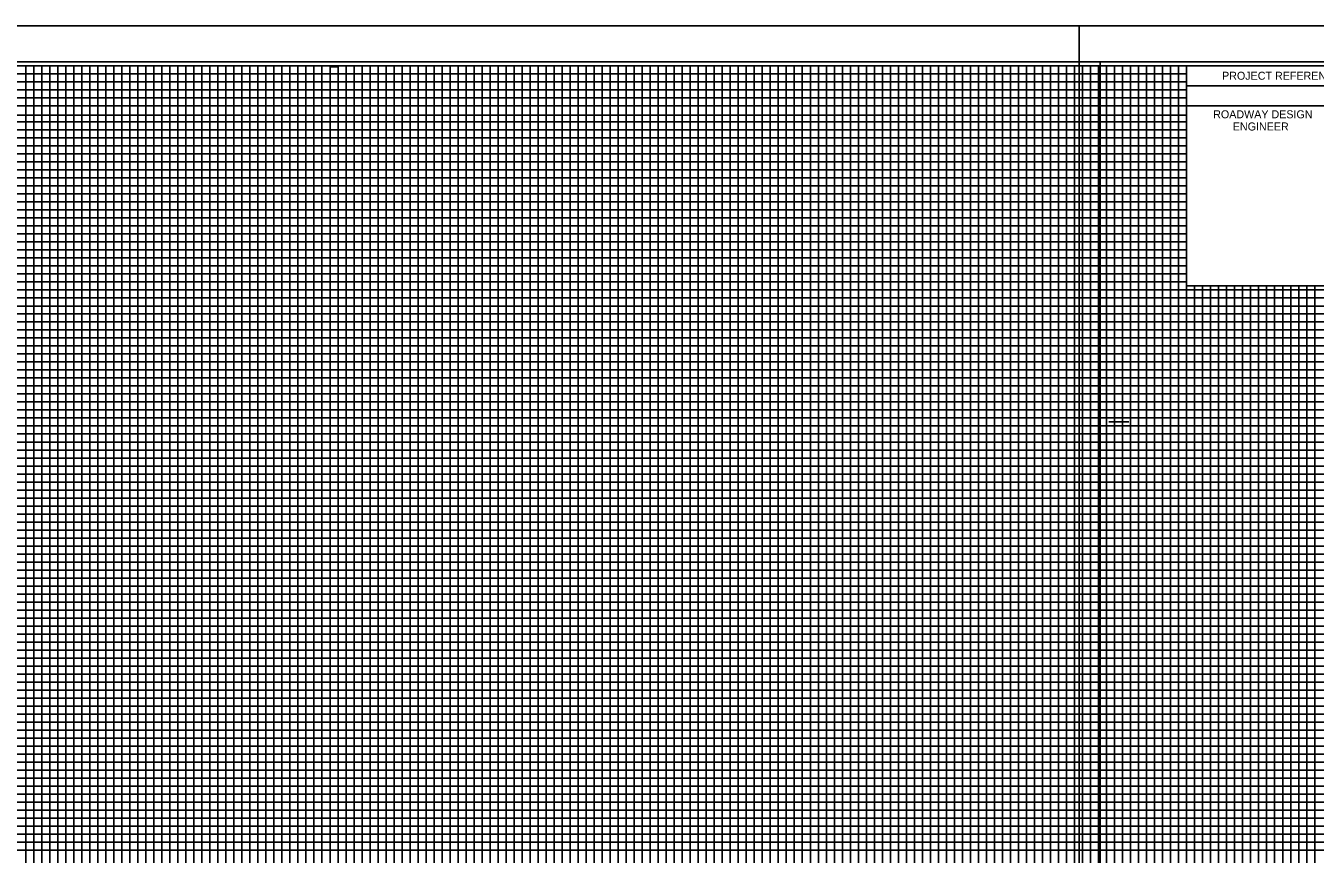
# Model space of a CAD drawing. Extents: x 2345490 to 2436403, y 465165 to 573888.
# Drawn here: x 2383692 to 2384497, y 501140 to 501658 of the extents above; entities that cross this region are included whole.
import ezdxf

# ---------------------------------------------------------------- set-up
doc = ezdxf.new("R2010")
doc.units = 0
for name, color, linetype in [('Old_Level_18', 7, 'Continuous'), ('Old_Level_40', 7, 'Continuous'), ('Old_Level_41', 7, 'Continuous'), ('Old_Level_42', 7, 'Continuous'), ('Old_Level_43', 7, 'Continuous'), ('Old_Level_44', 7, 'Continuous'), ('Old_Level_50', 7, 'Continuous'), ('Old_Level_51', 7, 'Continuous')]:
    doc.layers.add(name, color=color, linetype=linetype)

msp = doc.modelspace()

# ---------------------------------------------------------------- linework, layer by layer
at = {"layer": 'Old_Level_18'}
msp.add_lwpolyline([(2384616.79875, 501632.775), (2383116.79875, 501632.775), (2383116.79875, 500582.775), (2384616.79875, 500582.775)], close=True, dxfattribs=at)
at = {"layer": 'Old_Level_40'}
msp.add_line((2384416.74875, 501620.225), (2384616.79875, 501620.225), dxfattribs=at)
for points in [[(2384416.74875, 501632.775), (2384616.79875, 501632.775), (2384616.79875, 501607.725), (2384416.74875, 501607.725)], [(2384416.74875, 501607.725), (2384516.79875, 501607.725), (2384516.79875, 501495.225), (2384416.74875, 501495.225)]]:
    msp.add_lwpolyline(points, close=True, dxfattribs=at)
at = {"layer": 'Old_Level_41'}
msp.add_line((2384368.29875, 501410.275), (2384380.79875, 501410.275), dxfattribs=at)
for points in [[(2383691.79875, 500607.775), (2383691.79875, 501632.775), (2383741.79875, 501632.775), (2383741.79875, 500607.775)], [(2383716.79875, 500607.775), (2383716.79875, 501632.775), (2383766.79875, 501632.775), (2383766.79875, 500607.775)], [(2383791.79875, 500607.775), (2383791.79875, 501632.775), (2383841.79875, 501632.775), (2383841.79875, 500607.775)], [(2383816.79875, 500607.775), (2383816.79875, 501632.775), (2383866.79875, 501632.775), (2383866.79875, 500607.775)], [(2383891.79875, 500607.775), (2383891.79875, 501632.775), (2383941.79875, 501632.775), (2383941.79875, 500607.775)], [(2383916.79875, 500607.775), (2383916.79875, 501632.775), (2383966.79875, 501632.775), (2383966.79875, 500607.775)], [(2383991.79875, 500607.775), (2383991.79875, 501632.775), (2384041.79875, 501632.775), (2384041.79875, 500607.775)], [(2384016.79875, 500607.775), (2384016.79875, 501632.775), (2384066.79875, 501632.775), (2384066.79875, 500607.775)], [(2384091.79875, 500607.775), (2384091.79875, 501632.775), (2384141.79875, 501632.775), (2384141.79875, 500607.775)], [(2384116.79875, 500607.775), (2384116.79875, 501632.775), (2384166.79875, 501632.775), (2384166.79875, 500607.775)], [(2384191.79875, 500607.775), (2384191.79875, 501632.775), (2384241.79875, 501632.775), (2384241.79875, 500607.775)], [(2384216.79875, 500607.775), (2384216.79875, 501632.775), (2384266.79875, 501632.775), (2384266.79875, 500607.775)], [(2384291.79875, 500607.775), (2384291.79875, 501632.775), (2384341.79875, 501632.775), (2384341.79875, 500607.775)], [(2384316.79875, 500607.775), (2384316.79875, 501632.775), (2384366.79875, 501632.775), (2384366.79875, 500607.775)], [(2384391.79875, 500607.775), (2384391.79875, 501632.775)], [(2384416.79875, 500607.775), (2384416.79875, 501632.775), (2384443.09875, 501632.775)], [(2383116.79875, 501582.775), (2384416.74875, 501582.775)], [(2384416.74875, 501532.775), (2383116.79875, 501532.775), (2383116.79875, 501482.725), (2384616.79875, 501482.725)], [(2384616.79875, 501457.775), (2383116.79875, 501457.775), (2383116.79875, 501507.775), (2384416.74875, 501507.775)], [(2384441.79875, 501495.225), (2384441.79875, 500607.775), (2384491.79875, 500607.775), (2384491.79875, 501495.225)], [(2384616.79875, 501432.775), (2383116.79875, 501432.775), (2383116.79875, 501382.775), (2384616.79875, 501382.775)], [(2384616.79875, 501357.775), (2383116.79875, 501357.775), (2383116.79875, 501407.775), (2384616.79875, 501407.775)], [(2384616.79875, 501332.775), (2383116.79875, 501332.775), (2383116.79875, 501282.775), (2384616.79875, 501282.775)], [(2384616.79875, 501232.775), (2383116.79875, 501232.775), (2383116.79875, 501182.775), (2384616.79875, 501182.775)]]:
    msp.add_lwpolyline(points, dxfattribs=at)
at = {"layer": 'Old_Level_42'}
for points in [[(2384416.74875, 501557.775), (2383116.89875, 501557.775), (2383116.89875, 501607.725), (2384416.74875, 501607.725)], [(2384466.79875, 501495.225), (2384466.79875, 500607.775), (2384516.79875, 500607.775), (2384516.79875, 501495.225)], [(2384616.79875, 501257.775), (2383116.79875, 501257.775), (2383116.79875, 501307.775), (2384616.79875, 501307.775)], [(2384616.79875, 501157.775), (2383116.79875, 501157.775), (2383116.79875, 501207.775), (2384616.79875, 501207.775)]]:
    msp.add_lwpolyline(points, dxfattribs=at)
at = {"layer": 'Old_Level_43'}
for p, q in [((2384566.79875, 501452.775), (2383166.79875, 501452.775)), ((2383166.79875, 501447.775), (2384566.79875, 501447.775)), ((2384566.79875, 501427.775), (2383166.79875, 501427.775))]:
    msp.add_line(p, q, dxfattribs=at)
for points in [[(2383696.79875, 500607.775), (2383696.79875, 501632.775), (2383701.79875, 501632.775), (2383701.79875, 500607.775)], [(2383706.79875, 500607.775), (2383706.79875, 501632.775), (2383711.79875, 501632.775), (2383711.79875, 500607.775)], [(2383721.79875, 500607.775), (2383721.79875, 501632.775), (2383726.79875, 501632.775), (2383726.79875, 500607.775)], [(2383731.79875, 500607.775), (2383731.79875, 501632.775), (2383736.79875, 501632.775), (2383736.79875, 500607.775)], [(2383746.79875, 500607.775), (2383746.79875, 501632.775), (2383751.79875, 501632.775), (2383751.79875, 500607.775)], [(2383756.79875, 500607.775), (2383756.79875, 501632.775), (2383761.79875, 501632.775), (2383761.79875, 500607.775)], [(2383771.79875, 500607.775), (2383771.79875, 501632.775), (2383776.79875, 501632.775), (2383776.79875, 500607.775)], [(2383781.79875, 500607.775), (2383781.79875, 501632.775), (2383786.79875, 501632.775), (2383786.79875, 500607.775)], [(2383796.79875, 500607.775), (2383796.79875, 501632.775), (2383801.79875, 501632.775), (2383801.79875, 500607.775)], [(2383806.79875, 500607.775), (2383806.79875, 501632.775), (2383811.79875, 501632.775), (2383811.79875, 500607.775)], [(2383821.79875, 500607.775), (2383821.79875, 501632.775), (2383826.79875, 501632.775), (2383826.79875, 500607.775)], [(2383831.79875, 500607.775), (2383831.79875, 501632.775), (2383836.79875, 501632.775), (2383836.79875, 500607.775)], [(2383846.79875, 500607.775), (2383846.79875, 501632.775), (2383851.79875, 501632.775), (2383851.79875, 500607.775)], [(2383856.79875, 500607.775), (2383856.79875, 501632.775), (2383861.79875, 501632.775), (2383861.79875, 500607.775)], [(2383871.79875, 500607.775), (2383871.79875, 501632.775), (2383876.79875, 501632.775), (2383876.79875, 500607.775)], [(2383881.79875, 500607.775), (2383881.79875, 501632.175), (2383886.79875, 501632.175), (2383886.79875, 500607.775)], [(2383896.79875, 500607.775), (2383896.79875, 501632.775), (2383901.79875, 501632.775), (2383901.79875, 500607.775)], [(2383906.79875, 500607.775), (2383906.79875, 501632.775), (2383911.79875, 501632.775), (2383911.79875, 500607.775)], [(2383921.79875, 500607.775), (2383921.79875, 501632.775), (2383926.79875, 501632.775), (2383926.79875, 500607.775)], [(2383931.79875, 500607.775), (2383931.79875, 501632.775), (2383936.79875, 501632.775), (2383936.79875, 500607.775)], [(2383946.79875, 500607.775), (2383946.79875, 501632.775), (2383951.79875, 501632.775), (2383951.79875, 500607.775)], [(2383956.79875, 500607.775), (2383956.79875, 501632.775), (2383961.79875, 501632.775), (2383961.79875, 500607.775)], [(2383971.79875, 500607.775), (2383971.79875, 501632.775), (2383976.79875, 501632.775), (2383976.79875, 500607.775)], [(2383981.79875, 500607.775), (2383981.79875, 501632.775), (2383986.79875, 501632.775), (2383986.79875, 500607.775)], [(2383996.79875, 500607.775), (2383996.79875, 501632.775), (2384001.79875, 501632.775), (2384001.79875, 500607.775)], [(2384006.79875, 500607.775), (2384006.79875, 501632.775), (2384011.79875, 501632.775), (2384011.79875, 500607.775)], [(2384021.79875, 500607.775), (2384021.79875, 501632.775), (2384026.79875, 501632.775), (2384026.79875, 500607.775)], [(2384031.79875, 500607.775), (2384031.79875, 501632.775), (2384036.79875, 501632.775), (2384036.79875, 500607.775)], [(2384046.79875, 500607.775), (2384046.79875, 501632.775), (2384051.79875, 501632.775), (2384051.79875, 500607.775)], [(2384056.79875, 500607.775), (2384056.79875, 501632.775), (2384061.79875, 501632.775), (2384061.79875, 500607.775)], [(2384071.79875, 500607.775), (2384071.79875, 501632.775), (2384076.79875, 501632.775), (2384076.79875, 500607.775)], [(2384081.79875, 500607.775), (2384081.79875, 501632.775), (2384086.79875, 501632.775), (2384086.79875, 500607.775)], [(2384096.79875, 500607.775), (2384096.79875, 501632.775), (2384101.79875, 501632.775), (2384101.79875, 500607.775)], [(2384106.79875, 500607.775), (2384106.79875, 501632.775), (2384111.79875, 501632.775), (2384111.79875, 500607.775)], [(2384121.79875, 500607.775), (2384121.79875, 501632.775), (2384126.79875, 501632.775), (2384126.79875, 500607.775)], [(2384131.79875, 500607.775), (2384131.79875, 501632.775), (2384136.79875, 501632.775), (2384136.79875, 500607.775)], [(2384146.79875, 500607.775), (2384146.79875, 501632.775), (2384151.79875, 501632.775), (2384151.79875, 500607.775)], [(2384156.79875, 500607.775), (2384156.79875, 501632.775), (2384161.79875, 501632.775), (2384161.79875, 500607.775)], [(2384171.79875, 500607.775), (2384171.79875, 501632.775), (2384176.79875, 501632.775), (2384176.79875, 500607.775)], [(2384181.79875, 500607.775), (2384181.79875, 501632.775), (2384186.79875, 501632.775), (2384186.79875, 500607.775)], [(2384196.79875, 500607.775), (2384196.79875, 501632.775), (2384201.79875, 501632.775), (2384201.79875, 500607.775)], [(2384206.79875, 500607.775), (2384206.79875, 501632.775), (2384211.79875, 501632.775), (2384211.79875, 500607.775)], [(2384221.79875, 500607.775), (2384221.79875, 501632.775), (2384226.79875, 501632.775), (2384226.79875, 500607.775)], [(2384231.79875, 500607.775), (2384231.79875, 501632.775), (2384236.79875, 501632.775), (2384236.79875, 500607.775)], [(2384246.79875, 500607.775), (2384246.79875, 501632.775), (2384251.79875, 501632.775), (2384251.79875, 500607.775)], [(2384256.79875, 500607.775), (2384256.79875, 501632.775), (2384261.79875, 501632.775), (2384261.79875, 500607.775)], [(2384271.79875, 500607.775), (2384271.79875, 501632.775), (2384276.79875, 501632.775), (2384276.79875, 500607.775)], [(2384281.79875, 500607.775), (2384281.79875, 501632.775), (2384286.79875, 501632.775), (2384286.79875, 500607.775)], [(2384296.79875, 500607.775), (2384296.79875, 501632.775), (2384301.79875, 501632.775), (2384301.79875, 500607.775)], [(2384306.79875, 500607.775), (2384306.79875, 501632.775), (2384311.79875, 501632.775), (2384311.79875, 500607.775)], [(2384321.79875, 500607.775), (2384321.79875, 501632.775), (2384326.79875, 501632.775), (2384326.79875, 500607.775)], [(2384331.79875, 500607.775), (2384331.79875, 501632.775), (2384336.79875, 501632.775), (2384336.79875, 500607.775)], [(2384346.79875, 500607.775), (2384346.79875, 501632.775), (2384351.79875, 501632.775), (2384351.79875, 500607.775)], [(2384356.79875, 500607.775), (2384356.79875, 501632.775), (2384361.79875, 501632.775), (2384361.79875, 500607.775)], [(2384371.79875, 500607.775), (2384371.79875, 501632.775), (2384376.79875, 501632.775), (2384376.79875, 500607.775)], [(2384381.79875, 500607.775), (2384381.79875, 501632.775), (2384386.79875, 501632.775), (2384386.79875, 500607.775)], [(2384396.79875, 500607.775), (2384396.79875, 501632.775), (2384401.79875, 501632.775), (2384401.79875, 500607.775)], [(2384406.79875, 500607.775), (2384406.79875, 501632.775), (2384411.79875, 501632.775), (2384411.79875, 500607.775)], [(2384416.74875, 501627.775), (2383166.79875, 501627.775), (2383166.79875, 501622.775), (2384416.74875, 501622.775)], [(2384416.74875, 501617.775), (2383166.79875, 501617.775), (2383166.79875, 501612.775), (2384416.74875, 501612.775)], [(2384416.74875, 501602.025), (2383167.79875, 501602.025), (2383167.79875, 501597.775), (2384416.74875, 501597.775)], [(2384416.74875, 501592.775), (2383166.79875, 501592.775), (2383166.79875, 501587.775), (2384416.74875, 501587.775)], [(2384416.74875, 501577.775), (2383166.79875, 501577.775), (2383166.79875, 501572.775), (2384416.74875, 501572.775)], [(2384416.74875, 501567.775), (2383166.79875, 501567.775), (2383166.79875, 501562.775), (2384416.74875, 501562.775)], [(2384416.74875, 501552.775), (2383166.79875, 501552.775), (2383166.79875, 501547.775), (2384416.74875, 501547.775)], [(2384416.74875, 501542.775), (2383166.79875, 501542.775), (2383166.79875, 501537.775), (2384416.74875, 501537.775)], [(2384416.74875, 501527.775), (2383166.79875, 501527.775), (2383166.79875, 501522.775), (2384416.74875, 501522.775)], [(2384416.74875, 501517.775), (2383166.79875, 501517.775), (2383166.79875, 501512.775), (2384416.74875, 501512.775)], [(2384416.74875, 501502.775), (2383166.79875, 501502.775), (2383166.79875, 501497.775), (2384416.74875, 501497.775)], [(2384566.79875, 501492.775), (2383166.79875, 501492.775), (2383166.79875, 501492.775), (2383166.79875, 501472.775), (2384566.79875, 501472.775)], [(2384421.79875, 500607.775), (2384421.79875, 501495.225)], [(2384426.79875, 501495.225), (2384426.79875, 500607.775), (2384431.79875, 500607.775), (2384431.79875, 501495.225)], [(2384436.79875, 501495.225), (2384436.79875, 500607.775), (2384446.79875, 500607.775), (2384446.79875, 501495.225)], [(2384451.79875, 501495.225), (2384451.79875, 500607.775), (2384456.79875, 500607.775), (2384456.79875, 501495.225)], [(2384461.79875, 501495.225), (2384461.79875, 500607.775), (2384471.79875, 500607.775), (2384471.79875, 501495.225)], [(2384476.79875, 501495.225), (2384476.79875, 500607.775), (2384481.79875, 500607.775), (2384481.79875, 501495.225)], [(2384486.79875, 501495.225), (2384486.79875, 500607.775), (2384496.79875, 500607.775), (2384496.79875, 501495.225)], [(2383166.79875, 501487.775), (2384566.79875, 501487.775)], [(2384566.79875, 501477.775), (2383166.79875, 501477.775)], [(2384566.79875, 501467.775), (2383166.79875, 501467.775), (2383166.79875, 501462.775), (2384566.79875, 501462.775)], [(2384566.79875, 501442.775), (2383166.79875, 501442.775), (2383166.79875, 501437.775), (2384566.79875, 501437.775)], [(2384566.79875, 501422.775), (2383166.79875, 501422.775), (2383166.79875, 501417.775), (2384566.79875, 501417.775)], [(2384566.79875, 501412.775), (2383166.79875, 501412.775)], [(2383166.79875, 501402.775), (2384566.79875, 501402.775)], [(2384566.79875, 501397.775), (2383166.79875, 501397.775), (2383166.79875, 501392.775), (2384566.79875, 501392.775)], [(2384566.79875, 501387.775), (2383166.79875, 501387.775), (2383166.79875, 501377.775), (2384566.79875, 501377.775)], [(2384566.79875, 501372.775), (2383166.79875, 501372.775), (2383166.79875, 501367.775), (2384566.79875, 501367.775)], [(2384566.79875, 501362.775), (2383166.79875, 501362.775), (2383166.79875, 501352.775), (2384566.79875, 501352.775)], [(2384566.79875, 501347.775), (2383166.79875, 501347.775), (2383166.79875, 501342.775), (2384566.79875, 501342.775)], [(2384566.79875, 501337.775), (2383166.79875, 501337.775), (2383166.79875, 501327.775), (2384566.79875, 501327.775)], [(2384566.79875, 501322.775), (2383166.79875, 501322.775), (2383166.79875, 501317.775), (2384566.79875, 501317.775)], [(2384566.79875, 501312.775), (2383166.79875, 501312.775), (2383166.79875, 501302.775), (2384566.79875, 501302.775)], [(2384566.79875, 501297.775), (2383166.79875, 501297.775), (2383166.79875, 501292.775), (2384566.79875, 501292.775)], [(2384566.79875, 501287.775), (2383166.79875, 501287.775), (2383166.79875, 501277.775), (2384566.79875, 501277.775)], [(2384566.79875, 501272.775), (2383166.79875, 501272.775), (2383166.79875, 501267.775), (2384566.79875, 501267.775)], [(2384566.79875, 501262.775), (2383166.79875, 501262.775), (2383166.79875, 501252.775), (2384566.79875, 501252.775)], [(2384566.79875, 501247.775), (2383166.79875, 501247.775), (2383166.79875, 501242.775), (2384566.79875, 501242.775)], [(2384566.79875, 501237.775), (2383166.79875, 501237.775), (2383166.79875, 501227.775), (2384566.79875, 501227.775)], [(2384566.79875, 501222.775), (2383166.79875, 501222.775), (2383166.79875, 501217.775), (2384566.79875, 501217.775)], [(2384566.79875, 501212.775), (2383166.79875, 501212.775), (2383166.79875, 501202.775), (2384566.79875, 501202.775)], [(2384566.79875, 501197.775), (2383166.79875, 501197.775), (2383166.79875, 501192.775), (2384566.79875, 501192.775)], [(2384566.79875, 501187.775), (2383166.79875, 501187.775), (2383166.79875, 501177.775), (2384566.79875, 501177.775)], [(2384566.79875, 501172.775), (2383166.79875, 501172.775), (2383166.79875, 501167.775), (2384566.79875, 501167.775)], [(2384566.79875, 501162.775), (2383166.79875, 501162.775), (2383166.79875, 501152.775), (2384566.79875, 501152.775)], [(2384566.79875, 501147.775), (2383166.79875, 501147.775), (2383166.79875, 501142.775), (2384566.79875, 501142.775)]]:
    msp.add_lwpolyline(points, dxfattribs=at)
at = {"layer": 'Old_Level_50'}
for points in [[(2384629.29875, 501635.325), (2382962.79875, 501635.325), (2382962.79875, 500580.225), (2384629.29875, 500580.225)], [(2386029.29875, 501635.325), (2384362.79875, 501635.325), (2384362.79875, 500580.225), (2386029.29875, 500580.225)]]:
    msp.add_lwpolyline(points, close=True, dxfattribs=at)
at = {"layer": 'Old_Level_51'}
for points in [[(2384633.79875, 501657.775), (2382949.79875, 501657.775), (2382949.79875, 500557.775), (2384633.79875, 500557.775)], [(2386033.79875, 501657.775), (2384349.79875, 501657.775), (2384349.79875, 500557.775), (2386033.79875, 500557.775)]]:
    msp.add_lwpolyline(points, close=True, dxfattribs=at)

# ---------------------------------------------------------------- texts
at = {"layer": 'Old_Level_44'}
for s, p in [('PROJECT REFERENCE NO.', (2384438.94875, 501624.075)), ('ROADWAY DESIGN', (2384433.39875, 501599.975)), ('ENGINEER', (2384445.64875, 501592.375))]:
    msp.add_text(s, height=5.0001, dxfattribs=at).set_placement(p)

doc.saveas('drawing.dxf')
